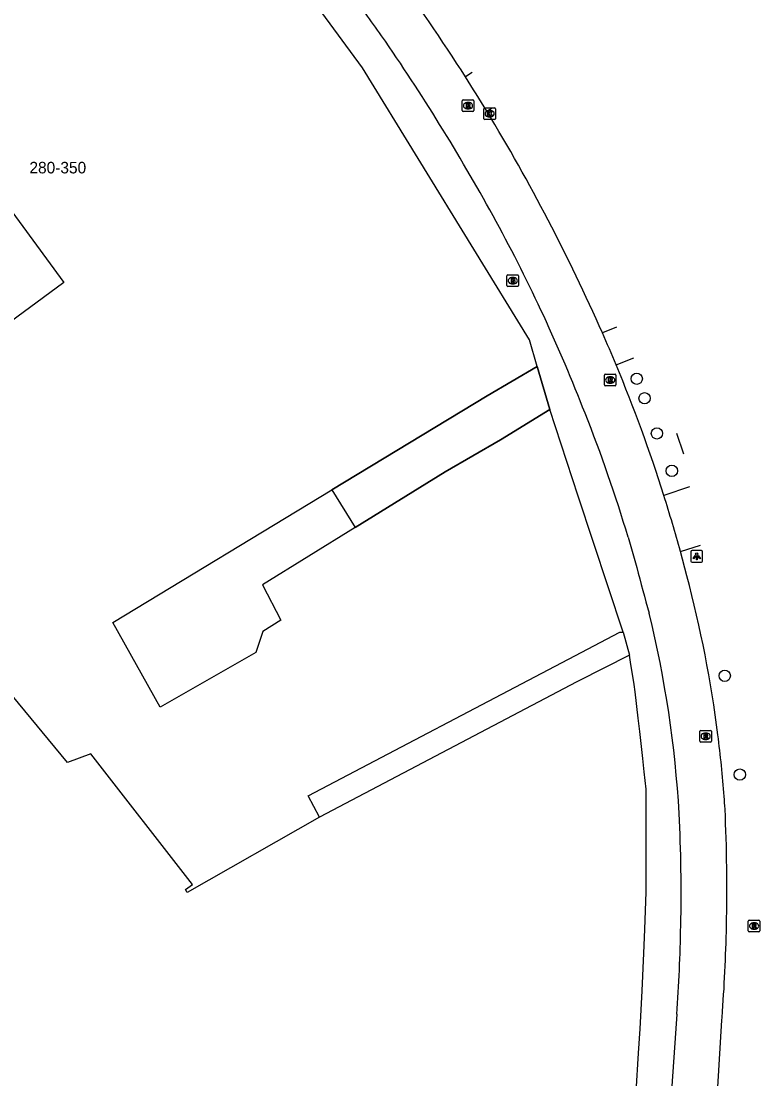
# Model space of a CAD drawing. Extents: x 161087 to 161922, y 382574 to 383873.
# Drawn here: x 161810.5 to 161874.3, y 382864 to 382955.4 of the extents above; entities that cross this region are included whole.
import ezdxf

# ---------------------------------------------------------------- set-up
doc = ezdxf.new("R2010")
doc.units = 0
for name, color, linetype in [('IMGEO_Berm_open', 7, 'Continuous'), ('IMGEO_Boom', 7, 'Continuous'), ('IMGEO_Brandkraan', 7, 'Continuous'), ('IMGEO_Fietspad_gesloten', 7, 'Continuous'), ('IMGEO_Kolk', 7, 'Continuous'), ('IMGEO_Lichtpunt', 7, 'Continuous'), ('IMGEO_Pand', 7, 'Continuous'), ('IMGEO_Pand_nummerreeks', 7, 'Continuous'), ('IMGEO_Pand_overbouw', 7, 'Continuous'), ('IMGEO_Rijbaan_lokaal_gesloten', 7, 'Continuous'), ('IMGEO_Rioolput', 7, 'Continuous'), ('IMGEO_Voetpad_open', 7, 'Continuous')]:
    doc.layers.add(name, color=color, linetype=linetype)

msp = doc.modelspace()

# ---------------------------------------------------------------- linework, layer by layer
at = {"layer": 'IMGEO_Berm_open'}
for points in [[(161849.456, 382950.963), (161848.875, 382950.597)], [(161850.723, 382947.626), (161851.186, 382947.909)], [(161861.929, 382928.95), (161860.719, 382928.455)], [(161861.904, 382925.699), (161863.426, 382926.309)], [(161868.256, 382915.158), (161866.032, 382914.408)], [(161867.465, 382909.566), (161869.198, 382910.119)]]:
    msp.add_lwpolyline(points, dxfattribs=at)
at = {"layer": 'IMGEO_Boom'}
for centre in [(161863.69, 382924.497), (161864.367, 382922.814), (161865.437, 382919.769), (161866.724, 382916.538), (161871.295, 382898.818), (161872.6, 382890.276)]:
    msp.add_circle(centre, 0.489, dxfattribs=at)
at = {"layer": 'IMGEO_Brandkraan'}
for p, q in [((161852.466, 382932.546), (161852.466, 382933.398)), ((161852.541, 382933.472), (161853.393, 382933.472)), ((161852.954, 382933.252), (161852.979, 382933.252)), ((161853.467, 382933.398), (161853.467, 382932.546)), ((161853.393, 382932.472), (161852.541, 382932.472)), ((161852.977, 382932.692), (161852.952, 382932.692))]:
    msp.add_line(p, q, dxfattribs=at)
for points in [[(161852.466, 382932.546), (161852.466, 382933.398)], [(161852.541, 382933.472), (161853.393, 382933.472)], [(161853.467, 382933.398), (161853.467, 382932.546)], [(161853.393, 382932.472), (161852.541, 382932.472)], [(161852.814, 382933.172), (161852.814, 382932.772), (161853.027, 382932.772)], [(161853.045, 382933.172), (161852.814, 382933.172)], [(161852.993, 382933.091), (161852.939, 382933.091), (161852.939, 382933.015)], [(161852.939, 382933.015), (161852.992, 382933.015)], [(161853.001, 382932.939), (161852.939, 382932.939), (161852.939, 382932.858)], [(161852.939, 382932.858), (161853.001, 382932.858)]]:
    msp.add_lwpolyline(points, dxfattribs=at)
for centre, radius, start, end in [((161852.543, 382933.396), 0.0765, 91.55205, 178.44795), ((161852.543, 382933.396), 0.0765, 91.55205, 178.44795), ((161853.391, 382933.396), 0.0765, 1.55205, 88.44795), ((161853.391, 382933.396), 0.0765, 1.55205, 88.44795), ((161852.543, 382932.548), 0.0765, 181.55205, 268.44795), ((161852.543, 382932.548), 0.0765, 181.55205, 268.44795), ((161852.994, 382933.053), 0.0379, 267.82845, 90.93552), ((161853.002, 382932.898), 0.0404, 269.87594, 90.50774), ((161853.033, 382933.023), 0.251, 268.66757, 293.53466), ((161853.049, 382933.027), 0.145, 59.4692, 91.53667), ((161853.074, 382933.074), 0.0922, 285.51372, 58.15012), ((161853.079, 382932.882), 0.105, 301.31148, 78.98903), ((161853.391, 382932.548), 0.0765, 271.55205, 358.44795), ((161853.391, 382932.548), 0.0765, 271.55205, 358.44795)]:
    msp.add_arc(centre, radius, start, end, dxfattribs=at)
for centre, major_axis, ratio, start_param, end_param in [((161852.953, 382932.972), (-0.387, 0.002), 0.722429, 4.712389, 7.853982), ((161852.978, 382932.972), (-0.39, 0.002), 0.717154, 1.570796, 4.712389)]:
    msp.add_ellipse(centre, major_axis=major_axis, ratio=ratio, start_param=start_param, end_param=end_param, dxfattribs=at)
at = {"layer": 'IMGEO_Fietspad_gesloten'}
for points in [[(161862.937, 382910.802), (161863.682, 382908.174)], [(161868.021, 382907.461), (161867.465, 382909.566)], [(161867.147, 382869.551), (161866.618, 382861.706), (161865.956, 382851.636)], [(161870.092, 382854.014), (161870.112, 382854.34), (161870.583, 382861.321), (161871.055, 382869.046), (161871.07, 382869.29)]]:
    msp.add_lwpolyline(points, dxfattribs=at)
for centre, radius, start, end in [((161709.468, 382861.777), 165.298, 32.5022, 36.44953), ((160188.576, 381768.05), 2034.548, 35.643851, 35.778073), ((161691.477, 382850.486), 182.464, 28.69239, 34.43848), ((161708.101, 382860.974), 166.882, 31.2815, 32.48278), ((161709.334, 382861.712), 165.445, 23.7917, 31.2845), ((161724.779, 382869.274), 144.231, 21.23547, 28.49665), ((161737.418, 382873.806), 134.869, 22.62906, 23.90354), ((161736.276, 382873.369), 136.091, 17.55095, 22.61397), ((161742.994, 382875.155), 125.128, 16.55185, 21.74641), ((161737.045, 382873.601), 135.288, 15.41689, 17.55557), ((162141.123, 382981.694), 287.017, 194.84176, 195.65616), ((161766.197, 382880.427), 105.352, 7.24266, 14.86879), ((161770.891, 382881.293), 96.628, 3.33684, 13.73666), ((161765.303, 382880.347), 106.248, 4.33925, 7.22473), ((161769.201, 382880.636), 102.34, 3.73093, 4.34326), ((161732.597, 382880.119), 134.929, 358.76437, 2.88805), ((161718.87, 382880.372), 152.612, 358.8067, 2.59995), ((161723.568, 382879.913), 143.952, 355.87235, 358.92389), ((161721.18, 382880.419), 150.303, 355.75357, 358.77039)]:
    msp.add_arc(centre, radius, start, end, dxfattribs=at)
at = {"layer": 'IMGEO_Kolk'}
for p, q in [((161850.54, 382947.907), (161851.392, 382947.907)), ((161850.465, 382946.981), (161850.465, 382947.833)), ((161850.976, 382947.127), (161850.951, 382947.127)), ((161850.953, 382947.687), (161850.978, 382947.687)), ((161851.466, 382947.833), (161851.466, 382946.981)), ((161851.392, 382946.907), (161850.54, 382946.907))]:
    msp.add_line(p, q, dxfattribs=at)
for points in [[(161850.54, 382947.907), (161851.392, 382947.907)], [(161850.465, 382946.981), (161850.465, 382947.833)], [(161850.786, 382947.607), (161850.909, 382947.607), (161850.909, 382947.456), (161851.039, 382947.607), (161851.203, 382947.607), (161851.057, 382947.456), (161851.21, 382947.207), (161851.058, 382947.207), (161850.973, 382947.371), (161850.909, 382947.304), (161850.909, 382947.207), (161850.786, 382947.207), (161850.786, 382947.607)], [(161851.466, 382947.833), (161851.466, 382946.981)], [(161851.392, 382946.907), (161850.54, 382946.907)]]:
    msp.add_lwpolyline(points, dxfattribs=at)
for centre, start, end in [((161850.542, 382947.831), 91.55205, 178.44795), ((161850.542, 382947.831), 91.55205, 178.44795), ((161851.39, 382947.831), 1.55205, 88.44795), ((161851.39, 382947.831), 1.55205, 88.44795), ((161850.542, 382946.983), 181.55205, 268.44795), ((161850.542, 382946.983), 181.55205, 268.44795), ((161851.39, 382946.983), 271.55205, 358.44795), ((161851.39, 382946.983), 271.55205, 358.44795)]:
    msp.add_arc(centre, 0.0765, start, end, dxfattribs=at)
for centre, major_axis, ratio, start_param, end_param in [((161850.952, 382947.407), (-0.387, 0.002), 0.722429, 4.712389, 7.853982), ((161850.977, 382947.407), (-0.39, 0.002), 0.717154, 1.570796, 4.712389)]:
    msp.add_ellipse(centre, major_axis=major_axis, ratio=ratio, start_param=start_param, end_param=end_param, dxfattribs=at)
at = {"layer": 'IMGEO_Lichtpunt'}
for p, q in [((161868.377, 382909.547), (161868.377, 382908.74)), ((161868.377, 382909.547), (161868.377, 382908.74)), ((161869.279, 382909.642), (161868.471, 382909.642)), ((161869.279, 382909.642), (161868.471, 382909.642)), ((161869.373, 382908.74), (161869.373, 382909.547)), ((161869.373, 382908.74), (161869.373, 382909.547)), ((161868.471, 382908.646), (161869.279, 382908.646)), ((161868.471, 382908.646), (161869.279, 382908.646))]:
    msp.add_line(p, q, dxfattribs=at)
for points in [[(161868.751, 382909.211), (161868.79, 382909.183), (161868.602, 382908.921), (161868.564, 382908.948), (161868.751, 382909.211)], [(161868.853, 382909.163), (161868.9, 382909.163), (161868.9, 382908.841), (161868.853, 382908.841), (161868.853, 382909.163)], [(161868.963, 382909.183), (161869.001, 382909.21), (161869.188, 382908.948), (161869.149, 382908.92), (161868.963, 382909.183)]]:
    msp.add_lwpolyline(points, dxfattribs=at)
msp.add_circle((161868.876, 382909.345), 0.0994, dxfattribs=at)
for centre, start, end in [((161868.471, 382909.547), 90, 180), ((161868.471, 382909.547), 90, 180), ((161869.279, 382909.547), 0, 90), ((161869.279, 382909.547), 0, 90), ((161868.471, 382908.74), 180, 270), ((161868.471, 382908.74), 180, 270), ((161869.279, 382908.74), 270, 0), ((161869.279, 382908.74), 270, 360)]:
    msp.add_arc(centre, 0.0946, start, end, dxfattribs=at)
at = {"layer": 'IMGEO_Pand'}
for points in [[(161855.067, 382925.568), (161854.42, 382927.865), (161839.98, 382951.379), (161816.402, 382983.483), (161815.661, 382984.111)], [(161796.626, 382956.694), (161814.151, 382932.831), (161808.285, 382928.523), (161807.905, 382929.167), (161805.553, 382930.844), (161784.088, 382965.443)], [(161856.165, 382921.851), (161851.909, 382919.229), (161847.115, 382916.463), (161839.326, 382911.629), (161831.331, 382906.668), (161832.906, 382903.613), (161831.356, 382902.656), (161830.74, 382900.821), (161822.483, 382896.118), (161818.373, 382903.439), (161837.306, 382914.885), (161850.765, 382923.021), (161855.067, 382925.568)], [(161862.526, 382902.582), (161858.634, 382914.359), (161856.165, 382921.851)], [(161836.245, 382886.593), (161835.279, 382888.433), (161857.791, 382900.256), (161862.217, 382902.58), (161862.526, 382902.582)], [(161863.049, 382900.607), (161858.618, 382898.343), (161858.518, 382898.291), (161836.245, 382886.593)], [(161863.645, 382862.837), (161863.846, 382866.18), (161863.973, 382868.294), (161864.17, 382871.573), (161864.3, 382874.847), (161864.381, 382876.895), (161864.509, 382880.15), (161864.507, 382881.852), (161864.501, 382886.117), (161864.496, 382889.026), (161864.331, 382890.515), (161864.204, 382891.654), (161863.943, 382894.002), (161863.813, 382895.165), (161863.56, 382897.441), (161863.461, 382898.057), (161863.146, 382900.003), (161863.049, 382900.607)], [(161836.245, 382886.593), (161824.819, 382880.088), (161824.675, 382880.355), (161825.263, 382880.78), (161816.481, 382892.083), (161814.47, 382891.319), (161809.669, 382897.124)]]:
    msp.add_lwpolyline(points, dxfattribs=at)
at = {"layer": 'IMGEO_Pand_overbouw'}
msp.add_lwpolyline([(161837.306, 382914.885), (161839.326, 382911.629), (161847.115, 382916.463), (161851.909, 382919.229), (161856.165, 382921.851), (161855.067, 382925.568), (161850.765, 382923.021)], close=True, dxfattribs=at)
at = {"layer": 'IMGEO_Rijbaan_lokaal_gesloten'}
msp.add_lwpolyline([(161867.113, 382919.802), (161867.723, 382918.011)], dxfattribs=at)
at = {"layer": 'IMGEO_Rioolput'}
for p, q in [((161848.596, 382947.676), (161848.596, 382948.528)), ((161848.671, 382948.602), (161849.523, 382948.602)), ((161849.084, 382948.382), (161849.109, 382948.382)), ((161849.597, 382948.528), (161849.597, 382947.676)), ((161849.523, 382947.602), (161848.671, 382947.602)), ((161849.107, 382947.822), (161849.082, 382947.822)), ((161860.89, 382923.961), (161860.89, 382924.813)), ((161860.965, 382924.887), (161861.817, 382924.887)), ((161861.401, 382924.107), (161861.376, 382924.107)), ((161861.378, 382924.667), (161861.403, 382924.667)), ((161861.891, 382924.813), (161861.891, 382923.961)), ((161861.817, 382923.887), (161860.965, 382923.887)), ((161869.149, 382893.165), (161869.149, 382894.017)), ((161869.224, 382894.091), (161870.076, 382894.091)), ((161870.15, 382894.017), (161870.15, 382893.165)), ((161870.076, 382893.091), (161869.224, 382893.091)), ((161869.66, 382893.311), (161869.635, 382893.311)), ((161869.637, 382893.871), (161869.662, 382893.871)), ((161873.332, 382876.762), (161873.332, 382877.614)), ((161873.407, 382877.688), (161874.259, 382877.688)), ((161874.333, 382877.614), (161874.333, 382876.762)), ((161874.259, 382876.688), (161873.407, 382876.688)), ((161873.843, 382876.908), (161873.818, 382876.908)), ((161873.82, 382877.468), (161873.845, 382877.468))]:
    msp.add_line(p, q, dxfattribs=at)
for points in [[(161848.596, 382947.676), (161848.596, 382948.528)], [(161848.671, 382948.602), (161849.523, 382948.602)], [(161849.185, 382948.3), (161848.933, 382948.302), (161848.933, 382947.902)], [(161848.933, 382947.902), (161849.057, 382947.902), (161849.057, 382948.064), (161849.068, 382948.064)], [(161849.111, 382948.221), (161849.057, 382948.221), (161849.057, 382948.14)], [(161849.057, 382948.14), (161849.109, 382948.14)], [(161849.115, 382948.035), (161849.186, 382947.902), (161849.326, 382947.902), (161849.261, 382948.028)], [(161849.597, 382948.528), (161849.597, 382947.676)], [(161849.523, 382947.602), (161848.671, 382947.602)], [(161860.89, 382923.961), (161860.89, 382924.813)], [(161860.965, 382924.887), (161861.817, 382924.887)], [(161861.479, 382924.585), (161861.227, 382924.587), (161861.227, 382924.187)], [(161861.227, 382924.187), (161861.351, 382924.187), (161861.351, 382924.349), (161861.362, 382924.349)], [(161861.405, 382924.506), (161861.351, 382924.506), (161861.351, 382924.425)], [(161861.351, 382924.425), (161861.403, 382924.425)], [(161861.409, 382924.32), (161861.48, 382924.187), (161861.62, 382924.187), (161861.555, 382924.313)], [(161861.891, 382924.813), (161861.891, 382923.961)], [(161861.817, 382923.887), (161860.965, 382923.887)], [(161869.149, 382893.165), (161869.149, 382894.017)], [(161869.224, 382894.091), (161870.076, 382894.091)], [(161870.15, 382894.017), (161870.15, 382893.165)], [(161870.076, 382893.091), (161869.224, 382893.091)], [(161869.738, 382893.789), (161869.486, 382893.791), (161869.486, 382893.391)], [(161869.486, 382893.391), (161869.61, 382893.391), (161869.61, 382893.553), (161869.621, 382893.553)], [(161869.664, 382893.71), (161869.61, 382893.71), (161869.61, 382893.629)], [(161869.61, 382893.629), (161869.662, 382893.629)], [(161869.668, 382893.524), (161869.739, 382893.391), (161869.879, 382893.391), (161869.814, 382893.517)], [(161873.332, 382876.762), (161873.332, 382877.614)], [(161873.407, 382877.688), (161874.259, 382877.688)], [(161874.333, 382877.614), (161874.333, 382876.762)], [(161874.259, 382876.688), (161873.407, 382876.688)], [(161873.921, 382877.386), (161873.669, 382877.388), (161873.669, 382876.988)], [(161873.669, 382876.988), (161873.793, 382876.988), (161873.793, 382877.15), (161873.804, 382877.15)], [(161873.847, 382877.307), (161873.793, 382877.307), (161873.793, 382877.226)], [(161873.793, 382877.226), (161873.845, 382877.226)], [(161873.851, 382877.121), (161873.922, 382876.988), (161874.062, 382876.988), (161873.997, 382877.114)]]:
    msp.add_lwpolyline(points, dxfattribs=at)
for centre, radius, start, end in [((161848.673, 382948.526), 0.0765, 91.55205, 178.44795), ((161848.673, 382948.526), 0.0765, 91.55205, 178.44795), ((161849.067, 382948.011), 0.0533, 26.02933, 88.69889), ((161849.093, 382948.329), 0.19, 274.7715, 282.96867), ((161849.117, 382948.125), 0.0964, 77.00612, 93.18647), ((161849.131, 382948.182), 0.0378, 276.66336, 79.67722), ((161849.184, 382948.19), 0.109, 350.36119, 89.41601), ((161849.182, 382948.19), 0.112, 277.58423, 350.98172), ((161849.166, 382947.975), 0.108, 29.51342, 73.79051), ((161849.521, 382948.526), 0.0765, 1.55205, 88.44795), ((161849.521, 382948.526), 0.0765, 1.55205, 88.44795), ((161848.673, 382947.678), 0.0765, 181.55205, 268.44795), ((161848.673, 382947.678), 0.0765, 181.55205, 268.44795), ((161849.521, 382947.678), 0.0765, 271.55205, 358.44795), ((161849.521, 382947.678), 0.0765, 271.55205, 358.44795), ((161860.967, 382924.811), 0.0765, 91.55205, 178.44795), ((161860.967, 382924.811), 0.0765, 91.55205, 178.44795), ((161861.361, 382924.296), 0.0533, 26.02933, 88.69889), ((161861.387, 382924.614), 0.19, 274.7715, 282.96867), ((161861.411, 382924.41), 0.0964, 77.00612, 93.18647), ((161861.425, 382924.467), 0.0378, 276.66336, 79.67722), ((161861.478, 382924.475), 0.109, 350.36119, 89.41601), ((161861.476, 382924.475), 0.112, 277.58423, 350.98172), ((161861.46, 382924.26), 0.108, 29.51342, 73.79051), ((161861.815, 382924.811), 0.0765, 1.55205, 88.44795), ((161861.815, 382924.811), 0.0765, 1.55205, 88.44795), ((161860.967, 382923.963), 0.0765, 181.55205, 268.44795), ((161860.967, 382923.963), 0.0765, 181.55205, 268.44795), ((161861.815, 382923.963), 0.0765, 271.55205, 358.44795), ((161861.815, 382923.963), 0.0765, 271.55205, 358.44795), ((161869.226, 382894.015), 0.0765, 91.55205, 178.44795), ((161869.226, 382894.015), 0.0765, 91.55205, 178.44795), ((161870.074, 382894.015), 0.0765, 1.55205, 88.44795), ((161870.074, 382894.015), 0.0765, 1.55205, 88.44795), ((161869.226, 382893.167), 0.0765, 181.55205, 268.44795), ((161869.226, 382893.167), 0.0765, 181.55205, 268.44795), ((161869.62, 382893.5), 0.0533, 26.02933, 88.69889), ((161869.646, 382893.818), 0.19, 274.7715, 282.96867), ((161869.67, 382893.614), 0.0964, 77.00612, 93.18647), ((161869.684, 382893.671), 0.0378, 276.66336, 79.67722), ((161869.737, 382893.679), 0.109, 350.36119, 89.41601), ((161869.735, 382893.679), 0.112, 277.58423, 350.98172), ((161869.719, 382893.464), 0.108, 29.51342, 73.79051), ((161870.074, 382893.167), 0.0765, 271.55205, 358.44795), ((161870.074, 382893.167), 0.0765, 271.55205, 358.44795), ((161873.409, 382877.612), 0.0765, 91.55205, 178.44795), ((161873.409, 382877.612), 0.0765, 91.55205, 178.44795), ((161874.257, 382877.612), 0.0765, 1.55205, 88.44795), ((161874.257, 382877.612), 0.0765, 1.55205, 88.44795), ((161873.409, 382876.764), 0.0765, 181.55205, 268.44795), ((161873.409, 382876.764), 0.0765, 181.55205, 268.44795), ((161873.803, 382877.097), 0.0533, 26.02933, 88.69889), ((161873.829, 382877.415), 0.19, 274.7715, 282.96867), ((161873.853, 382877.211), 0.0964, 77.00612, 93.18647), ((161873.867, 382877.268), 0.0378, 276.66336, 79.67722), ((161873.92, 382877.276), 0.109, 350.36119, 89.41601), ((161873.918, 382877.276), 0.112, 277.58423, 350.98172), ((161873.902, 382877.061), 0.108, 29.51342, 73.79051), ((161874.257, 382876.764), 0.0765, 271.55205, 358.44795), ((161874.257, 382876.764), 0.0765, 271.55205, 358.44795)]:
    msp.add_arc(centre, radius, start, end, dxfattribs=at)
for centre, major_axis, ratio, start_param, end_param in [((161849.083, 382948.102), (-0.387, 0.002), 0.722429, 4.712389, 7.853982), ((161849.108, 382948.102), (-0.39, 0.002), 0.717154, 1.570796, 4.712389), ((161861.377, 382924.387), (-0.387, 0.002), 0.722429, 4.712389, 7.853982), ((161861.402, 382924.387), (-0.39, 0.002), 0.717154, 1.570796, 4.712389), ((161869.636, 382893.591), (-0.387, 0.002), 0.722429, 4.712389, 7.853982), ((161869.661, 382893.591), (-0.39, 0.002), 0.717154, 1.570796, 4.712389), ((161873.819, 382877.188), (-0.387, 0.002), 0.722429, 4.712389, 7.853982), ((161873.844, 382877.188), (-0.39, 0.002), 0.717154, 1.570796, 4.712389)]:
    msp.add_ellipse(centre, major_axis=major_axis, ratio=ratio, start_param=start_param, end_param=end_param, dxfattribs=at)
at = {"layer": 'IMGEO_Voetpad_open'}
for points in [[(161855.067, 382925.568), (161856.165, 382921.851)], [(161862.526, 382902.582), (161863.049, 382900.607)]]:
    msp.add_lwpolyline(points, dxfattribs=at)

# ---------------------------------------------------------------- texts
at = {"layer": 'IMGEO_Pand_nummerreeks'}
msp.add_text('280-350', height=1, dxfattribs=at).set_placement((161811.167, 382942.25))

doc.saveas('drawing.dxf')
